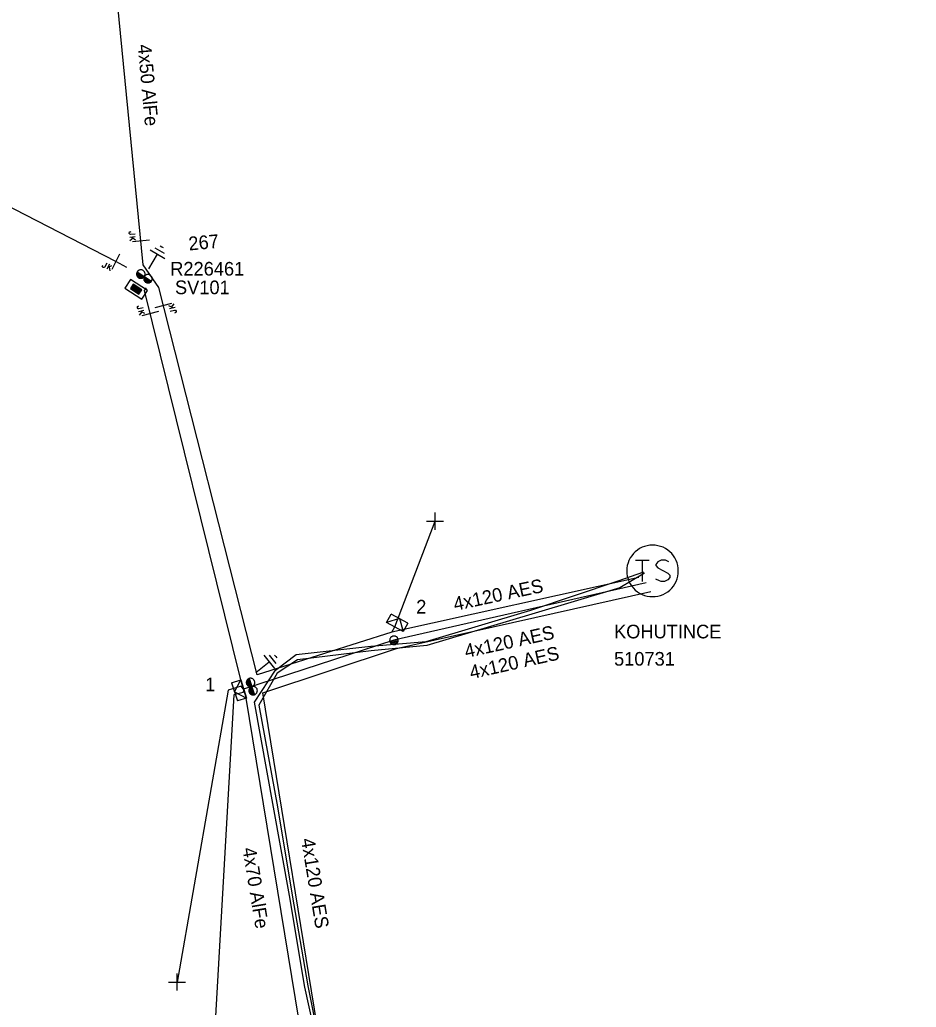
# Model space of a CAD drawing. Extents: x -544780 to -541582, y -1198995 to -1196551.
# Drawn here: x -542047.6 to -541981.8, y -1198729.6 to -1198657.1 of the extents above; entities that cross this region are included whole.
import ezdxf

# ---------------------------------------------------------------- set-up
doc = ezdxf.new("R2010")
doc.units = 0
for name, color, linetype in [('Vrstva 1', 7, 'Continuous'), ('Vrstva 13', 7, 'Continuous'), ('Vrstva 14', 7, 'Continuous'), ('Vrstva 15', 7, 'Continuous'), ('Vrstva 18', 7, 'Continuous'), ('Vrstva 2', 7, 'Continuous'), ('Vrstva 25', 7, 'Continuous'), ('Vrstva 26', 7, 'Continuous'), ('Vrstva 27', 7, 'Continuous'), ('Vrstva 28', 7, 'Continuous'), ('Vrstva 29', 7, 'Continuous'), ('Vrstva 30', 7, 'Continuous'), ('Vrstva 31', 7, 'Continuous'), ('Vrstva 34', 7, 'Continuous'), ('Vrstva 5', 7, 'Continuous'), ('Vrstva 50', 7, 'Continuous'), ('Vrstva 51', 7, 'Continuous'), ('Vrstva 54', 7, 'Continuous'), ('Vrstva 59', 7, 'Continuous'), ('Vrstva 6', 7, 'Continuous'), ('Vrstva 8', 7, 'Continuous'), ('Vrstva 9', 7, 'Continuous')]:
    doc.layers.add(name, color=color, linetype=linetype)

# ---------------------------------------------------------------- blocks, each defined once
blk = doc.blocks.new('NN440')
at = {"layer": 'Vrstva 2'}
for points in [[(0.63, 0), (0.63, 0.06), (0.62, 0.13), (0.6, 0.19), (0.58, 0.25), (0.55, 0.31), (0.51, 0.37), (0.47, 0.42), (0.42, 0.46), (0.37, 0.51), (0.32, 0.54), (0.26, 0.57), (0.2, 0.59), (0.13, 0.61), (0.07, 0.62), (0, 0.63), (-0.06, 0.62), (-0.13, 0.61), (-0.19, 0.59), (-0.26, 0.57), (-0.31, 0.54), (-0.37, 0.51), (-0.42, 0.46), (-0.47, 0.42), (-0.51, 0.37), (-0.54, 0.31), (-0.57, 0.25), (-0.6, 0.19), (-0.62, 0.13), (-0.63, 0.06), (-0.63, 0), (-0.63, -0.07), (-0.62, -0.14), (-0.6, -0.2), (-0.57, -0.26), (-0.54, -0.32), (-0.51, -0.37), (-0.47, -0.43), (-0.42, -0.47), (-0.37, -0.51), (-0.31, -0.55), (-0.26, -0.58), (-0.19, -0.6), (-0.13, -0.62), (-0.06, -0.63), (0, -0.63), (0.07, -0.63), (0.13, -0.62), (0.2, -0.6), (0.26, -0.58), (0.32, -0.55), (0.37, -0.51), (0.42, -0.47), (0.47, -0.43), (0.51, -0.37), (0.55, -0.32), (0.58, -0.26), (0.6, -0.2), (0.62, -0.14), (0.63, -0.07), (0.63, 0)], [(-0.63, 0), (0.63, 0)], [(-0.6, -0.18), (0.57, -0.18)], [(-0.51, -0.32), (0.5, -0.32)], [(-0.37, -0.47), (0.35, -0.47)]]:
    blk.add_lwpolyline(points, dxfattribs=at)
blk = doc.blocks.new('NN450')
at = {"layer": 'Vrstva 2'}
for points in [[(0, 0), (0, 0.07), (-0.01, 0.13), (-0.03, 0.19), (-0.05, 0.25), (-0.08, 0.31), (-0.12, 0.37), (-0.16, 0.42), (-0.21, 0.46), (-0.26, 0.51), (-0.31, 0.54), (-0.37, 0.57), (-0.43, 0.59), (-0.5, 0.61), (-0.56, 0.62), (-0.63, 0.62), (-0.69, 0.62), (-0.75, 0.61), (-0.82, 0.59), (-0.88, 0.57), (-0.94, 0.54), (-0.99, 0.51), (-1.04, 0.46), (-1.09, 0.42), (-1.13, 0.37), (-1.17, 0.31), (-1.2, 0.25), (-1.22, 0.19), (-1.24, 0.13), (-1.25, 0.07), (-1.25, 0), (-1.25, -0.07), (-1.24, -0.13), (-1.22, -0.19), (-1.2, -0.25), (-1.17, -0.31), (-1.13, -0.37), (-1.09, -0.42), (-1.04, -0.46), (-0.99, -0.51), (-0.94, -0.54), (-0.88, -0.57), (-0.82, -0.59), (-0.75, -0.61), (-0.69, -0.62), (-0.62, -0.63), (-0.56, -0.62), (-0.5, -0.61), (-0.43, -0.59), (-0.37, -0.57), (-0.31, -0.54), (-0.26, -0.51), (-0.21, -0.46), (-0.16, -0.42), (-0.12, -0.37), (-0.08, -0.31), (-0.05, -0.25), (-0.03, -0.19), (-0.01, -0.13), (0, -0.07), (0, 0)], [(1.25, 0), (1.25, 0.07), (1.24, 0.13), (1.22, 0.19), (1.2, 0.25), (1.17, 0.31), (1.13, 0.37), (1.09, 0.42), (1.04, 0.46), (0.99, 0.51), (0.94, 0.54), (0.88, 0.57), (0.82, 0.59), (0.75, 0.61), (0.69, 0.62), (0.62, 0.62), (0.56, 0.62), (0.5, 0.61), (0.43, 0.59), (0.37, 0.57), (0.31, 0.54), (0.26, 0.51), (0.21, 0.46), (0.16, 0.42), (0.12, 0.37), (0.08, 0.31), (0.05, 0.25), (0.03, 0.19), (0.01, 0.13), (0, 0.07), (0, 0), (0, -0.07), (0.01, -0.13), (0.03, -0.19), (0.05, -0.25), (0.08, -0.31), (0.12, -0.37), (0.16, -0.42), (0.21, -0.46), (0.26, -0.51), (0.31, -0.54), (0.37, -0.57), (0.43, -0.59), (0.5, -0.61), (0.56, -0.62), (0.63, -0.63), (0.69, -0.62), (0.75, -0.61), (0.82, -0.59), (0.88, -0.57), (0.94, -0.54), (0.99, -0.51), (1.04, -0.46), (1.09, -0.42), (1.13, -0.37), (1.17, -0.31), (1.2, -0.25), (1.22, -0.19), (1.24, -0.13), (1.25, -0.07), (1.25, 0)], [(-1.25, 0), (1.25, 0)], [(-1.23, -0.16), (-0.02, -0.16)], [(-1.16, -0.32), (-0.09, -0.32)], [(-1.03, -0.47), (-0.22, -0.47)], [(0.02, -0.16), (1.23, -0.16)], [(0.09, -0.32), (1.16, -0.32)], [(0.22, -0.47), (1.03, -0.47)]]:
    blk.add_lwpolyline(points, dxfattribs=at)
blk = doc.blocks.new('NN840')
at = {"layer": 'Vrstva 15'}
for points in [[(0.003, 0.619), (0.003, -0.631)], [(-0.745, -0.71), (-0.745, -0.66)], [(-0.73, -0.764), (-0.745, -0.71)], [(-0.538, -0.71), (-0.558, -0.764)], [(-0.538, -0.385), (-0.538, -0.71)], [(-0.332, -0.385), (-0.332, -0.798)], [(-0.332, -0.641), (-0.125, -0.385)], [(-0.263, -0.557), (-0.091, -0.798)], [(-0.657, -0.798), (-0.73, -0.764)], [(-0.627, -0.798), (-0.657, -0.798)], [(-0.558, -0.764), (-0.627, -0.798)]]:
    blk.add_lwpolyline(points, dxfattribs=at)
blk = doc.blocks.new('NN800')
at = {"layer": 'Vrstva 1'}
for points in [[(-0.442, 0.442), (0.442, -0.442)], [(-0.442, -0.442), (0.442, 0.442)]]:
    blk.add_lwpolyline(points, dxfattribs=at)
blk = doc.blocks.new('NN620')
at = {"layer": 'Vrstva 8'}
for points in [[(0.752, 0.004), (-0.748, 0.004)], [(-0.748, 0.004), (-0.748, -0.746)], [(0.752, -0.746), (0.752, 0.004)], [(0.368, -0.18), (-0.376, -0.18)], [(-0.376, -0.18), (-0.376, -0.558)], [(-0.376, -0.558), (0.368, -0.558)], [(0.321, -0.227), (-0.329, -0.227)], [(-0.329, -0.227), (-0.329, -0.51)], [(-0.329, -0.51), (0.321, -0.51)], [(0.274, -0.274), (-0.281, -0.274)], [(-0.281, -0.274), (-0.281, -0.463)], [(-0.281, -0.463), (0.274, -0.463)], [(0.227, -0.321), (-0.234, -0.321)], [(-0.234, -0.321), (-0.234, -0.416)], [(-0.234, -0.416), (0.227, -0.416)], [(-0.193, -0.369), (0.185, -0.369)], [(0.227, -0.416), (0.227, -0.321)], [(0.274, -0.463), (0.274, -0.274)], [(0.321, -0.51), (0.321, -0.227)], [(0.368, -0.558), (0.368, -0.18)], [(-0.748, -0.746), (0.752, -0.746)]]:
    blk.add_lwpolyline(points, dxfattribs=at)
blk = doc.blocks.new('NN630')
at = {"layer": 'Vrstva 9'}
for points in [[(-0.003, -0.7), (-0.703, 0)], [(-0.703, -0.7), (-0.703, 0), (0.697, 0), (0.697, -0.7)], [(-0.703, -0.7), (0.697, -0.7)], [(-0.003, -0.7), (0.697, 0)]]:
    blk.add_lwpolyline(points, dxfattribs=at)
blk = doc.blocks.new('NN810')
at = {"layer": 'Vrstva 14'}
for points in [[(0.004, -0.64), (0.004, -1.89)], [(0.629, -1.89), (-0.621, -1.89)], [(0.388, -2.2), (-0.399, -2.2)], [(0.004, -2.515), (-0.124, -2.515)], [(0.137, -2.515), (0.004, -2.515)]]:
    blk.add_lwpolyline(points, dxfattribs=at)
blk = doc.blocks.new('NN610')
at = {"layer": 'Vrstva 6'}
for points in [[(1.883, -0.001), (1.872, 0.196), (1.841, 0.392), (1.79, 0.583), (1.718, 0.768), (1.629, 0.943), (1.521, 1.109), (1.397, 1.263), (1.257, 1.403), (1.103, 1.527), (0.937, 1.635), (0.761, 1.725), (0.577, 1.796), (0.19, 1.878), (0.19, 1.878), (-0.007, 1.889), (-0.205, 1.878), (-0.401, 1.847), (-0.591, 1.796), (-0.777, 1.725), (-0.952, 1.635), (-1.118, 1.527), (-1.272, 1.403), (-1.412, 1.263), (-1.536, 1.109), (-1.644, 0.943), (-1.734, 0.768), (-1.805, 0.583), (-1.856, 0.392), (-1.887, 0.196), (-1.898, -0.001), (-1.887, -0.199), (-1.856, -0.395), (-1.805, -0.585), (-1.734, -0.77), (-1.644, -0.946), (-1.536, -1.112), (-1.411, -1.266), (-1.272, -1.405), (-1.118, -1.53), (-0.952, -1.638), (-0.776, -1.728), (-0.591, -1.799), (-0.401, -1.85), (-0.205, -1.881), (-0.007, -1.892), (0.19, -1.881), (0.385, -1.85), (0.577, -1.799), (0.761, -1.728), (0.937, -1.638), (1.103, -1.53), (1.257, -1.405), (1.397, -1.266), (1.521, -1.112), (1.629, -0.946), (1.718, -0.77), (1.79, -0.585), (1.841, -0.395), (1.872, -0.199), (1.883, -0.001)], [(-1.269, 0.782), (-0.261, 0.782)], [(-0.765, 0.782), (-0.765, -0.792)], [(1.188, 0.656), (0.936, 0.782), (0.621, 0.782), (0.369, 0.656), (0.243, 0.468), (0.243, 0.404), (0.369, 0.216), (1.125, -0.162), (1.251, -0.32), (1.251, -0.478), (1.125, -0.666), (0.873, -0.792), (0.621, -0.792), (0.495, -0.73), (0.243, -0.604)]]:
    blk.add_lwpolyline(points, dxfattribs=at)

msp = doc.modelspace()

# ---------------------------------------------------------------- linework, layer by layer
at = {"layer": 'Vrstva 1'}
for points in [[(-542039.715, -1198675.297), (-542040.534, -1198674.874), (-542063.64, -1198662.972), (-542087.392, -1198657.564), (-542117.714, -1198652.566), (-542142.478, -1198650.317), (-542153.843, -1198648.505), (-542165.606, -1198646.394), (-542176.658, -1198644.645), (-542189.959, -1198642.146), (-542195.053, -1198641.459), (-542204.232, -1198639.772), (-542208.416, -1198639.085), (-542219.219, -1198637.211), (-542230.022, -1198635.399), (-542250.833, -1198631.963), (-542269.04, -1198628.603), (-542276.533, -1198627.103), (-542287.898, -1198625.604), (-542301.672, -1198622.793), (-542314.536, -1198620.606), (-542337.89, -1198613.421)], [(-542038.52, -1198675.113), (-542040.848, -1198651.355)], [(-542031.162, -1198706.215), (-542031.371, -1198705.535), (-542038.438, -1198676.978), (-542038.296, -1198676.785)], [(-542016.418, -1198761.36), (-542026.577, -1198733.695), (-542030.995, -1198706.749), (-542031.162, -1198706.215)]]:
    msp.add_lwpolyline(points, dxfattribs=at)
at = {"layer": 'Vrstva 5'}
for points in [[(-542025.5, -1198733.41), (-542026.67, -1198728.07), (-542027.81, -1198721.35), (-542028.98, -1198714.88), (-542030.37, -1198707.18), (-542028.82, -1198704.82), (-542027.3, -1198703.68), (-542021.83, -1198703.07), (-542017.78, -1198702.74), (-542010.11, -1198700.44), (-542003.69, -1198698.29), (-542001.818, -1198697.613)], [(-542001.771, -1198697.72), (-542003.57, -1198698.79), (-542010.03, -1198700.73), (-542017.73, -1198703.03), (-542021.81, -1198703.42), (-542027.22, -1198704.07), (-542028.7, -1198705.05), (-542030.05, -1198707.39), (-542028.67, -1198714.85), (-542027.61, -1198721.33), (-542026.45, -1198727.99), (-542025.37, -1198733.34)]]:
    msp.add_lwpolyline(points, dxfattribs=at)
at = {"layer": 'Vrstva 50'}
for points in [[(-542002.171, -1198698.036), (-542020.29, -1198702.036), (-542030.178, -1198705.183), (-542037.376, -1198676.777), (-542038.52, -1198675.113)], [(-542001.653, -1198698.438), (-542020.136, -1198702.642), (-542031.162, -1198706.215)], [(-541850.821, -1198746.753), (-541864.747, -1198748.202), (-541878.673, -1198749.651), (-541899.566, -1198753.942), (-541928.472, -1198759.956), (-541943.718, -1198764.274), (-541958.963, -1198768.591), (-541978.85, -1198773.256), (-541998.738, -1198777.922), (-541999.244, -1198776.78), (-542015.406, -1198760.612), (-542025.386, -1198733.295), (-542029.761, -1198706.499), (-542019.948, -1198703.243), (-542001.308, -1198699.061)]]:
    msp.add_lwpolyline(points, dxfattribs=at)
at = {"layer": 'Vrstva 54'}
msp.add_lwpolyline([(-542020.29, -1198702.036), (-542020.084, -1198701.664)], dxfattribs=at)
at = {"layer": 'Vrstva 59'}
for points in [[(-542020.084, -1198701.664), (-542017.127, -1198693.904)], [(-542031.162, -1198706.214), (-542031.35, -1198706.008), (-542032.293, -1198706.298), (-542036.044, -1198727.704)], [(-542031.162, -1198706.215), (-542031.186, -1198706.466), (-542031.87, -1198706.649), (-542034.11, -1198745.64)]]:
    msp.add_lwpolyline(points, dxfattribs=at)

# ---------------------------------------------------------------- block references
at = {"layer": 'Vrstva 13', "yscale": 0.5}
for name, p, xscale, rotation in [('NN450', (-542038.437, -1198675.955), 0.49999999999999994, -33.142002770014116), ('NN440', (-542020.137, -1198702.642), 0.5, 14.650052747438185), ('NN450', (-542030.561, -1198706.036), 0.5, -72.58183611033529)]:
    msp.add_blockref(name, p, dxfattribs=dict(at, xscale=xscale, rotation=rotation))
at = {"layer": 'Vrstva 15'}
for p, rotation in [((-542038.437, -1198675.955), 149.7102777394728), ((-542030.758, -1198705.422), 129.17161105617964)]:
    msp.add_blockref('NN810', p, dxfattribs=dict(at, rotation=rotation))
at = {"layer": 'Vrstva 18'}
for p, rotation in [((-542038.692, -1198673.357), -84.76486114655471), ((-542040.534, -1198674.874), -26.74725284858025), ((-542038.016, -1198678.684), -76.10026944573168), ((-542037.044, -1198678.086), 104.21929173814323)]:
    msp.add_blockref('NN840', p, dxfattribs=dict(at, rotation=rotation))
at = {"layer": 'Vrstva 25', "rotation": 0.005377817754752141}
msp.add_blockref('NN610', (-542001.169, -1198697.549), dxfattribs=at)
at = {"layer": 'Vrstva 28', "rotation": -32.79599994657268}
msp.add_blockref('NN620', (-542038.843, -1198676.586), dxfattribs=at)
at = {"layer": 'Vrstva 31'}
for p, rotation in [((-542020.084, -1198701.664), 151.02391952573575), ((-542031.162, -1198706.214), -72.63375831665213)]:
    msp.add_blockref('NN630', p, dxfattribs=dict(at, rotation=rotation))
at = {"layer": 'Vrstva 34', "rotation": 45}
for p in [(-542017.127, -1198693.904), (-542036.044, -1198727.704)]:
    msp.add_blockref('NN800', p, dxfattribs=at)

# ---------------------------------------------------------------- texts
at = {"layer": 'Vrstva 14'}
msp.add_text('267', height=1, rotation=5.264, dxfattribs=at).set_placement((-542035.161, -1198674.058))
for s, p in [('2', (-542018.507, -1198700.679)), ('1', (-542033.981, -1198706.373))]:
    msp.add_text(s, height=1, dxfattribs=at).set_placement(p)
at = {"layer": 'Vrstva 2'}
for s, rotation, p in [('4x50 AlFe', 275.235, (-542038.936, -1198658.98)), ('4x70 AlFe', 279.311, (-542031.252, -1198717.909))]:
    msp.add_text(s, height=1, rotation=rotation, dxfattribs=at).set_placement(p)
at = {"layer": 'Vrstva 26'}
msp.add_text('510731', height=1, rotation=0.005, dxfattribs=at).set_placement((-542003.999, -1198704.5))
at = {"layer": 'Vrstva 27'}
msp.add_text('KOHUTINCE', height=1, rotation=0.005, dxfattribs=at).set_placement((-542003.999, -1198702.5))
at = {"layer": 'Vrstva 29'}
msp.add_text('R226461', height=1, rotation=359.948, dxfattribs=at).set_placement((-542036.545, -1198675.892))
at = {"layer": 'Vrstva 30'}
msp.add_text('SV101', height=1, rotation=359.948, dxfattribs=at).set_placement((-542036.197, -1198677.258))
at = {"layer": 'Vrstva 51'}
for rotation, p in [(12.049, (-542015.663, -1198700.486)), (12.353, (-542014.845, -1198703.945)), (12.645, (-542014.473, -1198705.498)), (279.273, (-542026.953, -1198717.23))]:
    msp.add_text('4x120 AES', height=1, rotation=rotation, dxfattribs=at).set_placement(p)

doc.saveas('drawing.dxf')
